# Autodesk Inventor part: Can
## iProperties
Created: 2008-06
Part Number: Can
Document SubType Name: Modeling
Density: 1 g/cm^3
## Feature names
1. Revolution1
2. Revolution2
3. Revolution3
4. Fillet1
5. Fillet2
